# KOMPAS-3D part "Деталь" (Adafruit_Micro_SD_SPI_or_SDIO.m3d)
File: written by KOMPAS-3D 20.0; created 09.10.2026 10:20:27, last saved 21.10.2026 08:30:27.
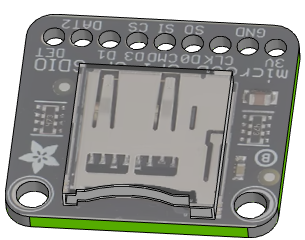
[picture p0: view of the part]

Document properties: Полное имя файла: D:\myProjects\Progect_esp32\box_compas\SD card\Adafruit_Micro_SD_SPI_or_SDIO.m3d

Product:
- Part/product: Деталь
    Масса: 0.0074136

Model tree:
1. Эскиз:1
2. Элемент выдавливания:1
     Расстояние 1 = 1.5
3. Эскиз:2  (with: Элемент выдавливания:1)
4. Элемент выдавливания:2
     Расстояние 2 = 1.5
5. Эскиз:3  (with: Элемент выдавливания:1)
6. Элемент выдавливания:3
     Расстояние 2 = 1.5
7. Массив по сетке:1  (with: Элемент выдавливания:3, Эскиз:3)  (9 pattern instances)
     Шаг 1 = 10; Угол раствора = -90; Шаг 2 = 2.54
8. Скругление:1  (with: Элемент выдавливания:1)
     Радиус = 2.5
9. Эскиз:5  (with: Элемент выдавливания:1)
10. Элемент выдавливания:4
     Расстояние 1 = 1.8
11. Эскиз:7  (with: Элемент выдавливания:4)
12. Элемент выдавливания:6
     Расстояние 2 = 13

Referenced files in D:\myProjects\Progect_esp32\box_compas\: Adafruit_Micro_SD_SPI_or_SDIO.png, socket_Micro_SD_up.png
